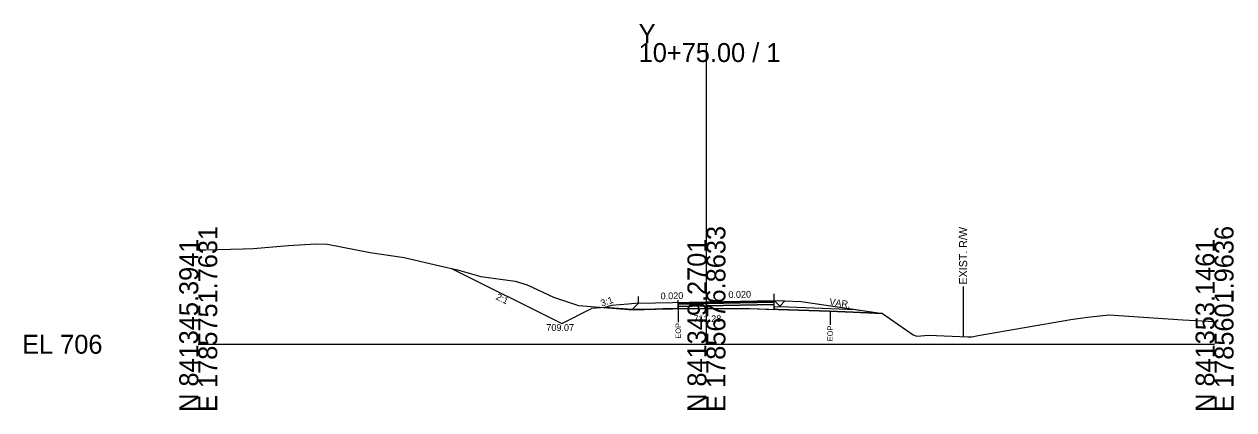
# Model space of a CAD drawing. Extents: x -26 to 153, y 990 to 3546.
# Drawn here: x -25.7 to 152.8, y 1490.3 to 1547.3 of the extents above; entities that cross this region are included whole.
import ezdxf

# ---------------------------------------------------------------- set-up
doc = ezdxf.new("R2010")
doc.units = 0
for name, color, linetype in [('Exist Cross Section Cell', 7, 'Continuous'), ('Exist XS Center Line Elevation Label', 7, 'Continuous'), ('Exist XS Ground Line', 7, 'Continuous'), ('Old_Level_10', 7, 'Continuous'), ('Prop XS DDE', 7, 'Continuous'), ('Prop XS Ditch Slope Text', 7, 'Continuous'), ('Prop XS Ditch Standard Text', 7, 'Continuous'), ('Prop XS Earthwork Shape', 7, 'Continuous'), ('Prop XS EOT Tick Mark', 7, 'Continuous'), ('Prop XS Finish Grade', 7, 'Continuous'), ('Prop XS Finish Grade Earthwork', 7, 'Continuous'), ('Prop XS Finish Grade Pavement', 7, 'Continuous'), ('Prop XS Hydro Fill Slope Data', 7, 'Continuous'), ('Prop XS Hydro Typical Ditch Data', 7, 'Continuous'), ('Prop XS Pvmt Edge Slope', 7, 'Continuous'), ('Prop XS SE Text', 7, 'Continuous'), ('Prop XS Subgrade Earthwork', 7, 'Continuous'), ('Scratch_Level_6', 7, 'Continuous')]:
    doc.layers.add(name, color=color, linetype=linetype)

msp = doc.modelspace()

# ---------------------------------------------------------------- linework, layer by layer
at = {"layer": 'Exist Cross Section Cell'}
for p, q in [((75, 1500), (75, 1544.51)), ((0, 1500), (75, 1500)), ((75, 1500), (150, 1500))]:
    msp.add_line(p, q, dxfattribs=at)
at = {"layer": 'Exist XS Ground Line'}
msp.add_lwpolyline([(0, 1513.97), (1.09, 1513.96), (6.65, 1514.11), (8.1, 1514.13), (13.3, 1514.61), (17.36, 1514.84), (19.09, 1514.79), (25.37, 1513.55), (30.41, 1512.84), (35.67, 1511.57), (38.28, 1511.01), (41.69, 1510.01), (46.75, 1509.34), (48.53, 1508.77), (52.44, 1506.95), (56.1, 1505.71), (64.2, 1505.1), (65.75, 1505.15), (66.34, 1505.21), (69.65, 1505.31), (70.79, 1505.29), (75, 1505.28), (76.66, 1505.28), (81.38, 1505.26), (85.58, 1505.13), (93.15, 1504.9), (96.68, 1504.74), (101, 1504.53), (105.5, 1501.41), (106.04, 1501.21), (107.77, 1501.35), (113.6, 1501.09), (114.18, 1501.12), (115.11, 1501.3), (128.79, 1503.65), (131.24, 1503.99), (134.46, 1504.33), (145.34, 1503.61), (150, 1503.34)], dxfattribs=at)
at = {"layer": 'Old_Level_10'}
for p, q in [((112.89, 1508.52), (112.89, 1501.12)), ((70.84, 1505.29), (70.84, 1503.24)), ((93.25, 1504.9), (93.25, 1502.85))]:
    msp.add_line(p, q, dxfattribs=at)
at = {"layer": 'Prop XS DDE'}
for p, q in [((37.4, 1511.2), (53.65, 1503.07)), ((53.65, 1503.07), (58.02, 1505.26)), ((60.02, 1505.41), (58.02, 1505.26))]:
    msp.add_line(p, q, dxfattribs=at)
at = {"layer": 'Prop XS Earthwork Shape'}
for points in [[(64.2, 1505.1), (65.75, 1505.15), (65.87, 1505.16), (64.06, 1505.13), (60.02, 1505.41)], [(70.84, 1505.29), (70.84, 1505.26), (65.87, 1505.16), (66.34, 1505.21), (69.65, 1505.31), (70.79, 1505.29)], [(97.03, 1505.12), (101, 1504.53), (96.68, 1504.74), (93.15, 1504.9), (85.58, 1505.13), (85, 1505.15), (85, 1505.55), (85.9, 1505.56)]]:
    msp.add_lwpolyline(points, close=True, dxfattribs=at)
at = {"layer": 'Prop XS EOT Tick Mark'}
for p, q in [((65, 1506.06), (65, 1507.06)), ((85, 1506.46), (85, 1507.46))]:
    msp.add_line(p, q, dxfattribs=at)
at = {"layer": 'Prop XS Finish Grade'}
for p, q in [((61, 1505.74), (60.02, 1505.41)), ((63.43, 1505.94), (61, 1505.74)), ((65, 1506.06), (63.43, 1505.94)), ((85, 1506.46), (86.57, 1506.4)), ((86.57, 1506.4), (89, 1506.3)), ((89, 1506.3), (97.03, 1505.12))]:
    msp.add_line(p, q, dxfattribs=at)
at = {"layer": 'Prop XS Finish Grade Earthwork'}
msp.add_line((97.03, 1505.12), (101, 1504.53), dxfattribs=at)
at = {"layer": 'Prop XS Finish Grade Pavement'}
for p, q in [((65, 1506.06), (75, 1506.26)), ((75, 1506.26), (85, 1506.46))]:
    msp.add_line(p, q, dxfattribs=at)
at = {"layer": 'Prop XS Hydro Fill Slope Data'}
msp.add_line((89, 1506.3), (101, 1504.53), dxfattribs=at)
at = {"layer": 'Prop XS Hydro Typical Ditch Data'}
msp.add_line((61, 1505.74), (60.02, 1505.41), dxfattribs=at)
at = {"layer": 'Prop XS Pvmt Edge Slope'}
for p, q in [((65, 1506.06), (64.06, 1505.13)), ((85, 1506.46), (85.9, 1505.56))]:
    msp.add_line(p, q, dxfattribs=at)
at = {"layer": 'Prop XS Subgrade Earthwork'}
for p, q in [((64.06, 1505.13), (60.02, 1505.41)), ((64.06, 1505.13), (70.84, 1505.26)), ((70.84, 1505.29), (70.84, 1505.26)), ((85, 1505.55), (85.9, 1505.56)), ((85, 1505.55), (85, 1505.15)), ((85.82, 1505.65), (86.57, 1506.4)), ((85.9, 1505.56), (97.03, 1505.12))]:
    msp.add_line(p, q, dxfattribs=at)
at = {"layer": 'Scratch_Level_6'}
for p, q in [((65.02, 1505.15), (75.02, 1505.35)), ((70.84, 1505.29), (70.84, 1506.54)), ((70.84, 1506.05), (75, 1506.14)), ((75, 1506.14), (70.84, 1506.05)), ((70.84, 1506.05), (70.84, 1505.93)), ((70.84, 1505.93), (75, 1506.01)), ((70.84, 1505.93), (75, 1506.01)), ((75, 1506.01), (70.84, 1505.93)), ((70.84, 1505.93), (70.84, 1505.6)), ((70.84, 1505.6), (75.01, 1505.68)), ((70.84, 1505.6), (75.01, 1505.68)), ((75.01, 1505.68), (70.84, 1505.6)), ((75, 1506.14), (85, 1506.34)), ((85, 1506.34), (75, 1506.14)), ((75, 1506.01), (85, 1506.21)), ((75, 1506.01), (85, 1506.21)), ((85, 1506.21), (75, 1506.01)), ((75.01, 1505.68), (85.01, 1505.88)), ((75.01, 1505.68), (85, 1505.88)), ((85, 1505.88), (75.01, 1505.68)), ((85, 1505.55), (85, 1506.8)), ((85, 1506.21), (85, 1506.34)), ((85, 1505.88), (85, 1506.21)), ((85, 1505.15), (85, 1505.55))]:
    msp.add_line(p, q, dxfattribs=at)
for points in [[(70.84, 1505.6), (70.84, 1505.35), (70.84, 1505.29)], [(70.84, 1505.29), (72.05, 1505.29), (75, 1505.28)], [(75, 1505.28), (76.66, 1505.28), (81.38, 1505.26), (85, 1505.15)], [(85, 1505.55), (85, 1505.63), (85, 1505.88)]]:
    msp.add_lwpolyline(points, dxfattribs=at)

# ---------------------------------------------------------------- texts
at = {"layer": 'Exist Cross Section Cell'}
for s, p in [('Y', (65, 1544.51)), ('10+75.00 / 1', (65, 1541.71)), ('EL 706', (-26, 1498.6))]:
    msp.add_text(s, height=2.8, dxfattribs=at).set_placement(p)
for s, p in [('E 1785751.7631', (2.8, 1490)), ('E 1785676.8633', (77.8, 1490)), ('E 1785601.9636', (152.8, 1490)), ('N 841345.3941', (0, 1490)), ('N 841349.2701', (75, 1490)), ('N 841353.1461', (150, 1490))]:
    msp.add_text(s, height=2.8, rotation=90, dxfattribs=at).set_placement(p)
at = {"layer": 'Exist XS Center Line Elevation Label'}
msp.add_text('711.28', height=1, dxfattribs=at).set_placement((73.1, 1503.28))
at = {"layer": 'Old_Level_10'}
for s, height, p in [('EXIST. R/W', 1.181, (113.48, 1508.82)), ('EOP', 0.787, (71.23, 1500.84)), ('EOP', 0.787, (93.65, 1500.45))]:
    msp.add_text(s, height=height, rotation=90, dxfattribs=at).set_placement(p)
at = {"layer": 'Prop XS Ditch Slope Text'}
for s, rotation, p in [('2:1', 333.4349, (43.82, 1506.69)), ('3:1', 18.4349, (59.57, 1505.56)), ('VAR.', 351.6115, (93.1, 1505.81))]:
    msp.add_text(s, height=1, rotation=rotation, dxfattribs=at).set_placement(p)
at = {"layer": 'Prop XS Ditch Standard Text'}
msp.add_text('709.07', height=1, dxfattribs=at).set_placement((51.37, 1501.97))
at = {"layer": 'Prop XS SE Text'}
for p in [(68.25, 1506.63), (78.25, 1506.83)]:
    msp.add_text('0.020', height=1, rotation=1.1458, dxfattribs=at).set_placement(p)

doc.saveas('drawing.dxf')
